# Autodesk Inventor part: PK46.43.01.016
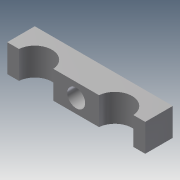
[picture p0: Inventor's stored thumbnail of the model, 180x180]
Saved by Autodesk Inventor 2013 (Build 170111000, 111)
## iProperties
Shininess: 64.0
Length Units: 11269
Angle Units: 11279
Time Units: 11290
Mass Units: 11283
Length Display Precision: 3
Angle Display Precision: 2
Compacted: True
Part Number: PK46.43.01.016
Document SubType Name: Modeling
Created: 2004-12
Material: Steel, High Strength Low Alloy
Designer: ELarisa
Manufacturer: Standard
Standards Organization: Custom
Density: 7.84 g/cm^3
Density: 0.0
Volumn: 0.0
Area: 0.0
PropertySet Name: Model Information
Control State: 0
Master: False
Checked Out: False
Checked Out Date: 2008-10-09
Last Check In Date: 2008-10-09
Author: ELarisa
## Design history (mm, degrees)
sketch "Эскиз3"
  geometry: L1 (82.501, -4.822)-(82.501, 15.178); L2 (-17.499, 15.178)-(-17.499, -4.822); L3 (82.501, 15.178)-(-17.499, 15.178); L4 (-17.499, -4.822)-(-8.959, -4.822); L5 (15.961, -4.822)-(49.041, -4.822); L6 (73.961, -4.822)-(82.501, -4.822); A1 r 12.5 centre (3.501, -5.822) between (15.961, -4.822) and (-8.959, -4.822); A2 r 12.5 centre (61.501, -5.822) between (73.961, -4.822) and (49.041, -4.822)
  constraints: 12 end point, 4 parallel, 4 point on circle, 3 horizontal, 3 perpendicular, 2 centre point, 2 collinear
  dimensions: "d17" = 100 distance between parallel lines of L1 L2; "d19" = 20 distance of L2.start L2.end; "d20" = 12.5 radius of A1; "d21" = 12.5 radius of A2; "d22" = 58 distance of A2.centre A1.centre; "d23" = 1 distance from line of A1.centre L4; "d24" = 1 distance from line of L6 A2.centre; "d25" = 21 distance from line of L2 A1.centre
extrude "Выдавливание2" new body sketch "Эскиз3" distance "d26" = 20; taper "d27" = 0 deg
sketch "Эскиз4"
  geometry: L1 (0, -20)-(100, -20) reference; L2 (0, 0)-(0, -20) reference; 1 further point
  dimensions: "d28" = 10 distance from line of point (50, -10) L1; "d29" = 50 distance from line of L2 point (50, -10)
hole "Отверстие2" sketch "Эскиз4" diameter "d30" = 13; stored, may be unused: countersink angle "d34" = 90 deg, drill point angle "d36" = 118 deg; dims "d31" = 6, "d32" = 16, "d33" = 2, "d35" = 8
body "Solid1"
